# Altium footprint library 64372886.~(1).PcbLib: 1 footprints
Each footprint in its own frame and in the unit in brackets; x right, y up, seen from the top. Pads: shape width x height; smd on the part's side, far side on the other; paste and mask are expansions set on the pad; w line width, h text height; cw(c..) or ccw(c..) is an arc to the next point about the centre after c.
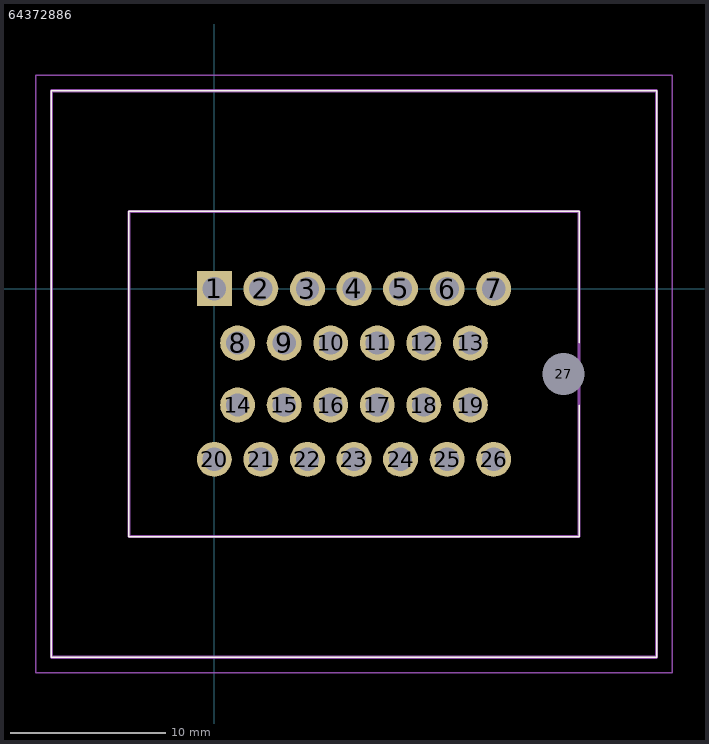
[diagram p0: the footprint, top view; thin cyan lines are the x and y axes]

## 64372886 [mm]
pads (27):
  rect 2.25x2.25 hole 1.5: 1(0,0)
  round 2.25 hole 1.5: 2(3,0) 3(6,0) 4(9,0) 5(12,0) 6(15,0) 7(18,0) 8(1.5,-3.5) 9(4.5,-3.5) 10(7.5,-3.5) 11(10.5,-3.5) 12(13.5,-3.5) 13(16.5,-3.5) 14(1.5,-7.5) 15(4.5,-7.5) 16(7.5,-7.5) 17(10.5,-7.5) 18(13.5,-7.5) 19(16.5,-7.5) 20(0,-11) 21(3,-11) 22(6,-11) 23(9,-11) 24(12,-11) 25(15,-11) 26(18,-11)
  round 1.35 hole 2.7 unplated: 27(22.5,-5.5)
Top Overlay:
  lines w0.1: 23.5,-7.5 23.5,-15.975 -5.5,-16 -5.5,4.975 23.5,4.975 23.5,-3.5 ; -10.5,-23.75 28.5,-23.75 28.5,12.75 -10.5,12.75 -10.5,-23.75
Mechanical 15:
  lines w0.2: -10.5,-23.75 28.5,-23.75 28.5,12.75 -10.5,12.75 -10.5,-23.75 ; -5.5,-15.975 23.5,-15.975 23.5,4.975 -5.5,4.975 -5.5,-15.975
Mechanical 20:
  lines w0.1: -11.5,-24.75 29.5,-24.75 29.5,13.75 -11.5,13.75 -11.5,-24.75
